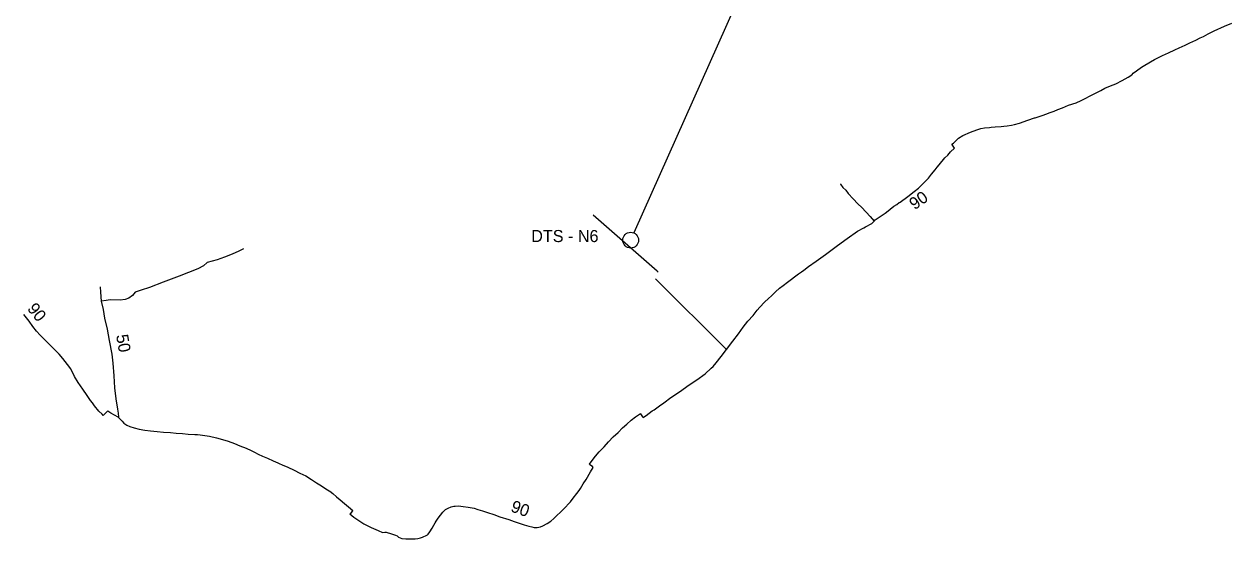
# Model space of a CAD drawing. Extents: x -444841 to -429545, y -1135312 to -1129851.
# Drawn here: x -442545 to -441745, y -1132207 to -1131866 of the extents above; entities that cross this region are included whole.
import ezdxf

# ---------------------------------------------------------------- set-up
doc = ezdxf.new("R2010")
doc.units = 0
for name, color, linetype in [('Vrstva 18', 7, 'Continuous'), ('Vrstva 19', 7, 'Continuous'), ('Vrstva 21', 7, 'Continuous'), ('Vrstva 27', 7, 'Continuous'), ('Vrstva 30', 7, 'Continuous'), ('Vrstva 35', 7, 'Continuous'), ('Vrstva 68', 7, 'Continuous')]:
    doc.layers.add(name, color=color, linetype=linetype)

msp = doc.modelspace()

# ---------------------------------------------------------------- linework, layer by layer
at = {"layer": 'Vrstva 18'}
msp.add_lwpolyline([(-441963.38, -1131605.66), (-442140.99, -1132004.1)], dxfattribs=at)
at = {"layer": 'Vrstva 19'}
msp.add_circle((-442143.13, -1132008.89), 5.25, dxfattribs=at)
at = {"layer": 'Vrstva 27'}
for points in [[(-441875, -1131927.67), (-441869.75, -1131926.05), (-441867.89, -1131925.4), (-441865.01, -1131924.31), (-441862.4, -1131923.32), (-441859.88, -1131922.32), (-441856.86, -1131921.13), (-441852.82, -1131919.46), (-441847.87, -1131917.74), (-441844.4, -1131916.28), (-441840.81, -1131914.45), (-441839.41, -1131913.62), (-441835.84, -1131911.74), (-441831.41, -1131909.53), (-441828.77, -1131908.18), (-441825.02, -1131906.55), (-441821.53, -1131905.26), (-441817.17, -1131903.05), (-441813.24, -1131900.85), (-441810.91, -1131899.22), (-441810.59, -1131898.98), (-441809.88, -1131898.1), (-441807.88, -1131896.6), (-441804.44, -1131894.11), (-441802.14, -1131892.73), (-441795.87, -1131889.1), (-441790.46, -1131886.42), (-441786.58, -1131884.62), (-441782.27, -1131882.58), (-441779.42, -1131881.29), (-441775.47, -1131879.49), (-441772.41, -1131877.99), (-441768.49, -1131876.15), (-441765.58, -1131874.69), (-441763.43, -1131873.71), (-441760.19, -1131872.06), (-441756.2, -1131870.05), (-441749.53, -1131867.03), (-441744.56, -1131864.94)], [(-441981.67, -1131996.21), (-441981.02, -1131995.45), (-441977.8, -1131993.13), (-441974.42, -1131990.88), (-441973.47, -1131990.27), (-441968.62, -1131986.43), (-441966.74, -1131985.13), (-441965.12, -1131983.99), (-441964.55, -1131983.6), (-441959.44, -1131980.02), (-441955.22, -1131976.58), (-441952.28, -1131974.36), (-441949.4, -1131971.51), (-441947.6, -1131969.77), (-441945.6, -1131967.7), (-441943.64, -1131965.01), (-441941.3, -1131962.34), (-441939.86, -1131960.55), (-441938.51, -1131958.85), (-441934.73, -1131954.37), (-441932.91, -1131952.49), (-441931.17, -1131950.38), (-441928.46, -1131947.97), (-441930.3, -1131945.2), (-441929.11, -1131944.46), (-441926.78, -1131942.29), (-441925.72, -1131941.34), (-441922.95, -1131939.52), (-441917.81, -1131937.3), (-441913.73, -1131935.73), (-441910.87, -1131934.94), (-441908.58, -1131934.49), (-441905.3, -1131934.06), (-441904.06, -1131933.9), (-441901.53, -1131933.83), (-441897.38, -1131933.48), (-441895.62, -1131933.32), (-441893.43, -1131933.03), (-441890.54, -1131932.51), (-441888.6, -1131932.1), (-441885.31, -1131931.25), (-441879.9, -1131929.41), (-441875.39, -1131927.79), (-441875, -1131927.67)], [(-442003.99, -1131971.63), (-442003.91, -1131971.77), (-442002.38, -1131973.94), (-442000.46, -1131975.73), (-441999, -1131977.99), (-441995.67, -1131981.48), (-441992.56, -1131984.9), (-441989.93, -1131987.27), (-441984.44, -1131993.17), (-441981.67, -1131996.21)], [(-441987.35, -1132000), (-441983.31, -1131997.75), (-441982.2, -1131996.77), (-441981.67, -1131996.21)], [(-442237.95, -1132189.53), (-442233.92, -1132190.84), (-442229.77, -1132192.31), (-442223.98, -1132194.24), (-442220.24, -1132195.46), (-442216.93, -1132196.59), (-442213.64, -1132197.69), (-442210.66, -1132198.54), (-442208.68, -1132199.03), (-442207.04, -1132199.38), (-442205.09, -1132199.4), (-442202.93, -1132198.96), (-442201.3, -1132198.33), (-442198.53, -1132196.78), (-442196.11, -1132195.25), (-442193.99, -1132193.56), (-442187.68, -1132187.28), (-442183.1, -1132182.34), (-442181.24, -1132179.93), (-442178.7, -1132176.96), (-442177.26, -1132175), (-442176.3, -1132173.67), (-442174.51, -1132170.53), (-442172.67, -1132167.55), (-442169.83, -1132162.49), (-442167.97, -1132159.63), (-442168.42, -1132159.1), (-442170.13, -1132157.88), (-442170.38, -1132157.39), (-442168.73, -1132155.07), (-442166.52, -1132152.2), (-442163.91, -1132149.2), (-442160.79, -1132145.85), (-442157.78, -1132142.75), (-442154.66, -1132139.36), (-442151.49, -1132136.36), (-442148.6, -1132133.39), (-442145.76, -1132130.88), (-442142.75, -1132128.38), (-442139.9, -1132126.1), (-442136.65, -1132123.83), (-442136.52, -1132124), (-442135.17, -1132126.07), (-442134.79, -1132126.44), (-442133.29, -1132125.46), (-442132.83, -1132125.09), (-442130.88, -1132123.53), (-442128.79, -1132122.15), (-442127.58, -1132121.35), (-442123.92, -1132118.74), (-442121.23, -1132116.7), (-442116.41, -1132113.33), (-442110.74, -1132109.42), (-442104.27, -1132104.83), (-442099.23, -1132101.47), (-442093.74, -1132097.45), (-442089.73, -1132093.88), (-442089.65, -1132093.84), (-442088.51, -1132092.61), (-442086.41, -1132090.19), (-442083.15, -1132086.08), (-442079.53, -1132081.31), (-442075.33, -1132075.87), (-442071.72, -1132070.94), (-442068.51, -1132066.66), (-442065.34, -1132062.71), (-442061.87, -1132058.78), (-442060.54, -1132057.02), (-442059.21, -1132055.41), (-442057.38, -1132053.31), (-442054.34, -1132050.07), (-442051.82, -1132047.61), (-442049.83, -1132045.73), (-442048.7, -1132044.66), (-442047.19, -1132043.13), (-442044.47, -1132040.76), (-442042.07, -1132038.88), (-442039.12, -1132036.77), (-442031.91, -1132031.33), (-442029.87, -1132029.91), (-442028.24, -1132028.69), (-442025.29, -1132026.46), (-442020.09, -1132022.74), (-442013.87, -1132018.31), (-442005.99, -1132012.41), (-441999.6, -1132007.83), (-441992.69, -1132002.98), (-441988.45, -1132000.61), (-441987.35, -1132000)], [(-442399.75, -1132014.71), (-442402.92, -1132016.19), (-442407.32, -1132018.24), (-442412.39, -1132020.22), (-442417.33, -1132021.83), (-442423.83, -1132023.62), (-442426.29, -1132025.88), (-442429.98, -1132027.89), (-442442.39, -1132032.84), (-442453.04, -1132036.85), (-442462.06, -1132040.35), (-442467.64, -1132042.11), (-442471.59, -1132043.3), (-442473.35, -1132045.63), (-442475.77, -1132047.32), (-442478.29, -1132048.31), (-442481.64, -1132048.64), (-442488.24, -1132048.4), (-442490.87, -1132048.97), (-442494.06, -1132049.39)], [(-442494.91, -1132039.85), (-442494.61, -1132043.28), (-442494.06, -1132049.39), (-442492.87, -1132054.81), (-442491.9, -1132060.55), (-442490.06, -1132067.97), (-442488.75, -1132075.41), (-442487.15, -1132084.45), (-442486.35, -1132090.55), (-442485.79, -1132098.87), (-442485.26, -1132106.89), (-442484.33, -1132114.02), (-442483.37, -1132121.05), (-442482.91, -1132123.59), (-442482.73, -1132126.38)], [(-442500, -1132116.78), (-442501.13, -1132115.32), (-442503.47, -1132111.98), (-442506.35, -1132107.69), (-442509.35, -1132103.26), (-442511.72, -1132099.36), (-442514.26, -1132094.3), (-442516.39, -1132091.3), (-442519.56, -1132087.46), (-442522.04, -1132084.51), (-442525.35, -1132081.13), (-442527.74, -1132078.76), (-442530.69, -1132075.93), (-442534.67, -1132071.81), (-442536.94, -1132069.23), (-442539.38, -1132066.07), (-442541.82, -1132062.57), (-442545.37, -1132058.16)], [(-442482.73, -1132126.38), (-442482.95, -1132126.21), (-442487.76, -1132123.62), (-442489.8, -1132122.22), (-442490.22, -1132122.48), (-442492.28, -1132124.7), (-442492.91, -1132125.28), (-442493.54, -1132124.36), (-442495.71, -1132122.25), (-442498.49, -1132118.73), (-442500, -1132116.78)], [(-442482.73, -1132126.38), (-442482.56, -1132126.51), (-442481.82, -1132127.35), (-442480.17, -1132129.03), (-442479.03, -1132130.26), (-442477.07, -1132131.49), (-442475.06, -1132132.37), (-442472.34, -1132133.3), (-442468.98, -1132134.26), (-442465.23, -1132134.92), (-442461.54, -1132135.27), (-442457.06, -1132135.87), (-442452.89, -1132136.22), (-442448.27, -1132136.52), (-442444.43, -1132136.86), (-442440.29, -1132137.21), (-442436.58, -1132137.51), (-442432.14, -1132137.81), (-442430.2, -1132137.7), (-442428.6, -1132138.07), (-442425.52, -1132138.47), (-442422.29, -1132138.88), (-442417.68, -1132139.92), (-442413.68, -1132141.07), (-442410.06, -1132142.31), (-442405.73, -1132143.79), (-442402.21, -1132145.22), (-442397.93, -1132146.95), (-442394.8, -1132148.3), (-442392.59, -1132149.53), (-442390.13, -1132150.74), (-442387.21, -1132152.22), (-442383.96, -1132153.55), (-442380.18, -1132155.23), (-442377.08, -1132156.62), (-442376.04, -1132157.05), (-442374.16, -1132157.86), (-442370.4, -1132159.52), (-442366.26, -1132161.37), (-442362.36, -1132163.33), (-442358.54, -1132165.28), (-442354.68, -1132167.54), (-442351.45, -1132169.75), (-442348.05, -1132171.93), (-442345.11, -1132173.78), (-442343, -1132175.21), (-442342.6, -1132175.47), (-442340.67, -1132177.01), (-442338.21, -1132179.02), (-442335.65, -1132181.13), (-442332.93, -1132183.45), (-442330.21, -1132185.75), (-442327.23, -1132188.15), (-442327.51, -1132188.31), (-442329.11, -1132190.3), (-442329.31, -1132190.47), (-442326.6, -1132192.62), (-442323.33, -1132194.86), (-442319.92, -1132197), (-442315.08, -1132199.45), (-442310.49, -1132201.46), (-442307.6, -1132202.69), (-442306.03, -1132202.56), (-442305.18, -1132202.49), (-442301.67, -1132203.67), (-442299.11, -1132204.63), (-442298.02, -1132205.05), (-442296.92, -1132205.87), (-442294.79, -1132206.65), (-442292.2, -1132206.99), (-442290.6, -1132206.96), (-442289.87, -1132206.95), (-442287.41, -1132206.94), (-442285.92, -1132206.87), (-442284.29, -1132206.79), (-442282.44, -1132206.25), (-442281.01, -1132205.87), (-442278.16, -1132204.5), (-442277.83, -1132204.22), (-442277.33, -1132203.94), (-442276.19, -1132202.37), (-442274.75, -1132200), (-442273.7, -1132197.99), (-442272.83, -1132196.39), (-442272.12, -1132195.15), (-442270.7, -1132193.33), (-442269.23, -1132191.23), (-442267.72, -1132189.34), (-442265.98, -1132187.58), (-442264.18, -1132186.58), (-442262.07, -1132185.67), (-442260.28, -1132185.29), (-442259.45, -1132185.22), (-442257.16, -1132185.1), (-442254.12, -1132185.5), (-442250.78, -1132185.88), (-442248.22, -1132186.38), (-442246.92, -1132186.69), (-442244.36, -1132187.55), (-442241.37, -1132188.48), (-442237.95, -1132189.53)]]:
    msp.add_lwpolyline(points, dxfattribs=at)
at = {"layer": 'Vrstva 35'}
msp.add_line((-442079.53, -1132081.31), (-442126.76, -1132034.54), dxfattribs=at)
at = {"layer": 'Vrstva 68'}
msp.add_lwpolyline([(-442124.89, -1132030.14), (-442125.55, -1132029.47), (-442168.03, -1131992.28)], dxfattribs=at)

# ---------------------------------------------------------------- texts
at = {"layer": 'Vrstva 21'}
msp.add_text('DTS - N6', height=8, dxfattribs=at).set_placement((-442209.02, -1132010.15))
at = {"layer": 'Vrstva 30'}
for s, rotation, p in [('90', 35.01459, (-441954.88, -1131989.1)), ('90', 308.83367, (-442543.57, -1132054.48)), ('50', 280.0369, (-442484.31, -1132072.07)), ('90', 340.495, (-442223.18, -1132188.68))]:
    msp.add_text(s, height=8, rotation=rotation, dxfattribs=at).set_placement(p)

doc.saveas('drawing.dxf')
